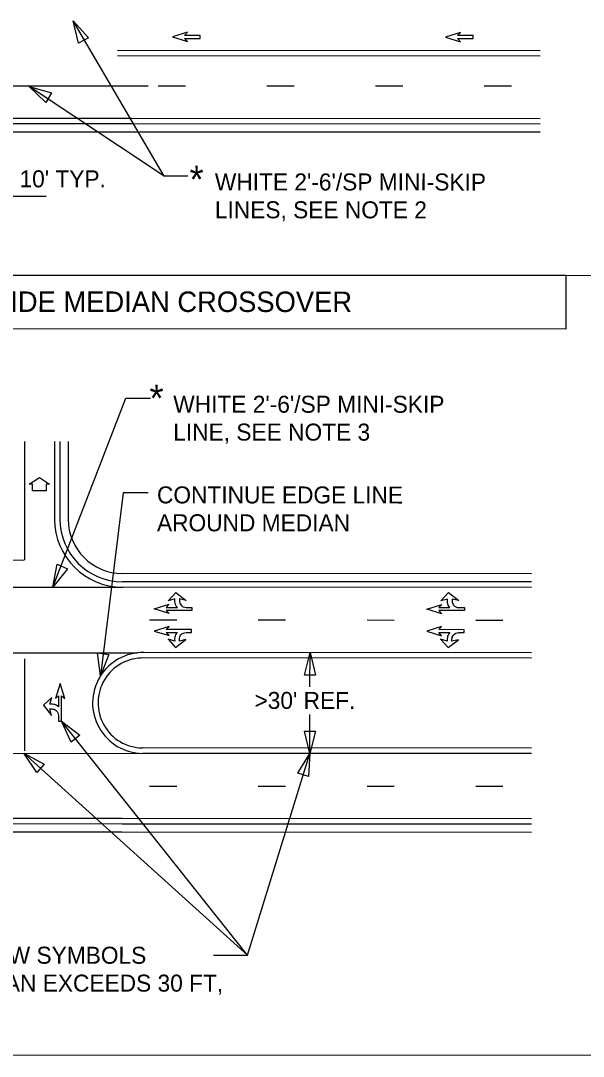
# Model space of a CAD drawing. Extents: x 50667 to 52386, y 46650 to 50479.
# Drawn here: x 51216.8 to 51454.8, y 46906.1 to 47344.1 of the extents above; entities that cross this region are included whole.
import ezdxf

# ---------------------------------------------------------------- set-up
doc = ezdxf.new("R2010")
doc.units = 0
for name, color, linetype in [('Default', 7, 'Continuous'), ('DEV TUBULAR MARKER SECTIONAL VIEW CELL', 7, 'Continuous'), ('Exist Hydro Spring Leader', 7, 'Continuous'), ('Exist Hydro Spring Text', 7, 'Continuous'), ('Gray Area Fill Shapes', 7, 'Continuous'), ('Matchline', 7, 'Continuous'), ('Prop EOT Dash', 7, 'Continuous'), ('Sheet North Arrow CELL', 7, 'Continuous')]:
    doc.layers.add(name, color=color, linetype=linetype)

msp = doc.modelspace()

# ---------------------------------------------------------------- linework, layer by layer
at = {"layer": 'Default'}
for p, q in [((51277.48, 47278.32), (51238.97, 47344.14)), ((51436.58, 47331.45), (51257.71, 47331.53)), ((51436.58, 47329.15), (51257.71, 47329.23)), ((51277.48, 47278.32), (51220.33, 47316.29)), ((51263.44, 47302.78), (51005.23, 47302.9)), ((51436.57, 47302.7), (51263.44, 47302.78)), ((51263.44, 47300.48), (51005.23, 47300.6)), ((51436.56, 47300.4), (51263.44, 47300.48)), ((51263.44, 47297.03), (51005.22, 47297.15)), ((51436.56, 47296.95), (51263.44, 47297.03)), ((51287.53, 47278.32), (51277.48, 47278.32)), ((51149.49, 47269.92), (51227.55, 47269.88)), ((52075.41, 47236.01), (50973.63, 47236.53)), ((51230.36, 47104.52), (51261.3, 47184.43)), ((51261.3, 47184.43), (51271.68, 47184.42)), ((51218.44, 47166.2), (51218.42, 47116.03)), ((51231.09, 47166.19), (51231.07, 47133.27)), ((51233.39, 47166.19), (51233.37, 47133.27)), ((51236.84, 47166.19), (51236.82, 47133.27)), ((51260.11, 47144.39), (51250.5, 47066.99)), ((51270.75, 47144.38), (51260.11, 47144.39)), ((51197.72, 47116.04), (51218.13, 47116.03)), ((51432.98, 47110.18), (51259.81, 47110.26)), ((51432.98, 47106.73), (51259.81, 47106.81)), ((51432.98, 47104.43), (51259.81, 47104.51)), ((51432.96, 47076.83), (51268.93, 47076.9)), ((51339.18, 47062.41), (51339.19, 47076.87)), ((51218.4, 47074.28), (51218.38, 47035.37)), ((51432.96, 47074.53), (51268.93, 47074.6)), ((51339.17, 47034.21), (51339.17, 47050.69)), ((51312.71, 46948.87), (51234.01, 47047.85)), ((51432.95, 47036.47), (51268.32, 47036.54)), ((51312.71, 46948.87), (51218.09, 47034.27)), ((51432.94, 47034.17), (51268.32, 47034.24)), ((51312.71, 46948.87), (51339.17, 47034.21)), ((51259.76, 47006.65), (51001.59, 47006.77)), ((51432.93, 47006.57), (51259.76, 47006.65)), ((51259.76, 47004.35), (51001.59, 47004.47)), ((51259.76, 47000.9), (51001.59, 47001.02)), ((51432.93, 47004.27), (51259.76, 47004.35)), ((51432.93, 47000.82), (51259.76, 47000.9)), ((51298.42, 46948.87), (51312.71, 46948.87))]:
    msp.add_line(p, q, dxfattribs=at)
for points in [[(51274.95, 47316.58), (51286.45, 47316.57)], [(51320.95, 47316.55), (51332.45, 47316.55)], [(51366.95, 47316.53), (51378.45, 47316.53)], [(51412.95, 47316.56), (51424.45, 47316.55)], [(51271.3, 47090.7), (51282.8, 47090.7)], [(51317.3, 47090.68), (51328.8, 47090.68)], [(51363.35, 47090.66), (51374.85, 47090.65)], [(51409.35, 47090.64), (51420.85, 47090.63)], [(51271.27, 47020.44), (51282.77, 47020.44)], [(51317.27, 47020.42), (51328.77, 47020.41)], [(51363.32, 47020.4), (51374.82, 47020.39)], [(51409.32, 47020.38), (51420.82, 47020.37)]]:
    msp.add_lwpolyline(points, dxfattribs=at)
for centre, radius, start, end in [((51259.84, 47133.3), 28.75, 179.9734, 269.9734), ((51259.84, 47133.3), 26.45, 179.9734, 269.9734), ((51259.84, 47133.3), 23, 179.9734, 269.9734), ((51268.52, 47055.57), 21.33, 88.898, 269.4602), ((51268.52, 47055.57), 19.03, 88.898, 269.4602)]:
    msp.add_arc(centre, radius, start, end, dxfattribs=at)
at = {"layer": 'DEV TUBULAR MARKER SECTIONAL VIEW CELL'}
for points in [[(50879.23, 46906.71), (50879.58, 47676.39), (52169.91, 47675.79), (52169.55, 46906.11)], [(50973.62, 47214), (51447.58, 47213.78), (51447.59, 47236.31), (50973.63, 47236.53)]]:
    msp.add_lwpolyline(points, close=True, dxfattribs=at)
at = {"layer": 'Exist Hydro Spring Leader'}
for p, q in [((51168.97, 47076.79), (51266.17, 47076.78)), ((51166.52, 47034.29), (51268.32, 47034.24))]:
    msp.add_line(p, q, dxfattribs=at)
at = {"layer": 'Exist Hydro Spring Text'}
for p, q in [((51171.06, 47316.61), (51270.68, 47316.57)), ((51174.73, 47104.59), (51259.83, 47104.55))]:
    msp.add_line(p, q, dxfattribs=at)
at = {"layer": 'Gray Area Fill Shapes'}
msp.add_lwpolyline([(51221.81, 47145.23), (51221.81, 47148.1), (51220.38, 47148.1), (51224.74, 47150.97), (51229, 47148.1), (51227.56, 47148.1), (51227.56, 47145.22)], close=True, dxfattribs=at)
at = {"layer": 'Matchline'}
for points in [[(51289.18, 47094.7), (51278.38, 47094.7), (51279.62, 47093.35), (51273.29, 47095.33), (51279.62, 47097.3), (51278.38, 47095.95), (51283.08, 47095.95), (51282.62, 47096.52), (51282.36, 47096.96), (51282.17, 47097.52), (51282.07, 47097.97), (51281.99, 47098.55), (51282.01, 47099.58), (51279.21, 47098.75), (51282.43, 47102.28), (51286.79, 47098.96), (51283.99, 47099.58), (51284, 47098.77), (51284.02, 47098.29), (51284.14, 47097.81), (51284.36, 47097.4), (51284.6, 47096.98), (51285.04, 47096.56), (51285.58, 47096.24), (51286.15, 47096.04), (51286.81, 47095.94), (51289.18, 47095.94)], [(51289.18, 47094.7), (51278.38, 47094.7), (51279.62, 47093.35), (51273.29, 47095.33), (51279.62, 47097.3), (51278.38, 47095.95), (51283.08, 47095.95), (51282.62, 47096.52), (51282.36, 47096.96), (51282.17, 47097.52), (51282.07, 47097.97), (51281.99, 47098.55), (51282.01, 47099.58), (51279.21, 47098.75), (51282.43, 47102.28), (51286.79, 47098.96), (51283.99, 47099.58), (51284, 47098.77), (51284.02, 47098.29), (51284.14, 47097.81), (51284.36, 47097.4), (51284.6, 47096.98), (51285.04, 47096.56), (51285.58, 47096.24), (51286.15, 47096.04), (51286.81, 47095.94), (51289.18, 47095.94)], [(51404.52, 47094.64), (51393.72, 47094.65), (51394.97, 47093.3), (51388.64, 47095.28), (51394.97, 47097.24), (51393.73, 47095.9), (51398.42, 47095.89), (51397.97, 47096.46), (51397.71, 47096.9), (51397.51, 47097.46), (51397.41, 47097.92), (51397.33, 47098.5), (51397.36, 47099.53), (51394.56, 47098.7), (51397.78, 47102.23), (51402.14, 47098.9), (51399.33, 47099.53), (51399.35, 47098.72), (51399.37, 47098.24), (51399.49, 47097.76), (51399.71, 47097.34), (51399.95, 47096.92), (51400.38, 47096.5), (51400.92, 47096.18), (51401.5, 47095.98), (51402.16, 47095.88), (51404.52, 47095.89)], [(51404.52, 47094.64), (51393.72, 47094.65), (51394.97, 47093.3), (51388.64, 47095.28), (51394.97, 47097.24), (51393.73, 47095.9), (51398.42, 47095.89), (51397.97, 47096.46), (51397.71, 47096.9), (51397.51, 47097.46), (51397.41, 47097.92), (51397.33, 47098.5), (51397.36, 47099.53), (51394.56, 47098.7), (51397.78, 47102.23), (51402.14, 47098.9), (51399.33, 47099.53), (51399.35, 47098.72), (51399.37, 47098.24), (51399.49, 47097.76), (51399.71, 47097.34), (51399.95, 47096.92), (51400.38, 47096.5), (51400.92, 47096.18), (51401.5, 47095.98), (51402.16, 47095.88), (51404.52, 47095.89)], [(51289.09, 47086.62), (51278.3, 47086.62), (51279.54, 47087.97), (51273.21, 47086), (51279.54, 47084.03), (51278.3, 47085.38), (51283, 47085.37), (51282.54, 47084.8), (51282.28, 47084.37), (51282.08, 47083.81), (51281.98, 47083.35), (51281.9, 47082.77), (51281.93, 47081.74), (51279.13, 47082.57), (51282.34, 47079.04), (51286.7, 47082.36), (51283.9, 47081.74), (51283.92, 47082.55), (51283.94, 47083.03), (51284.06, 47083.51), (51284.28, 47083.92), (51284.52, 47084.34), (51284.95, 47084.76), (51285.49, 47085.08), (51286.07, 47085.28), (51286.73, 47085.38), (51289.09, 47085.37)], [(51289.09, 47086.62), (51278.3, 47086.62), (51279.54, 47087.97), (51273.21, 47086), (51279.54, 47084.03), (51278.3, 47085.38), (51283, 47085.37), (51282.54, 47084.8), (51282.28, 47084.37), (51282.08, 47083.81), (51281.98, 47083.35), (51281.9, 47082.77), (51281.93, 47081.74), (51279.13, 47082.57), (51282.34, 47079.04), (51286.7, 47082.36), (51283.9, 47081.74), (51283.92, 47082.55), (51283.94, 47083.03), (51284.06, 47083.51), (51284.28, 47083.92), (51284.52, 47084.34), (51284.95, 47084.76), (51285.49, 47085.08), (51286.07, 47085.28), (51286.73, 47085.38), (51289.09, 47085.37)], [(51404.44, 47086.56), (51393.64, 47086.57), (51394.89, 47087.92), (51388.56, 47085.95), (51394.89, 47083.97), (51393.64, 47085.32), (51398.34, 47085.32), (51397.89, 47084.75), (51397.63, 47084.31), (51397.43, 47083.75), (51397.33, 47083.29), (51397.25, 47082.72), (51397.28, 47081.69), (51394.47, 47082.52), (51397.69, 47078.99), (51402.05, 47082.31), (51399.25, 47081.69), (51399.26, 47082.49), (51399.28, 47082.97), (51399.4, 47083.45), (51399.62, 47083.87), (51399.86, 47084.29), (51400.3, 47084.71), (51400.84, 47085.03), (51401.42, 47085.23), (51402.08, 47085.33), (51404.44, 47085.32)], [(51404.44, 47086.56), (51393.64, 47086.57), (51394.89, 47087.92), (51388.56, 47085.95), (51394.89, 47083.97), (51393.64, 47085.32), (51398.34, 47085.32), (51397.89, 47084.75), (51397.63, 47084.31), (51397.43, 47083.75), (51397.33, 47083.29), (51397.25, 47082.72), (51397.28, 47081.69), (51394.47, 47082.52), (51397.69, 47078.99), (51402.05, 47082.31), (51399.25, 47081.69), (51399.26, 47082.49), (51399.28, 47082.97), (51399.4, 47083.45), (51399.62, 47083.87), (51399.86, 47084.29), (51400.3, 47084.71), (51400.84, 47085.03), (51401.42, 47085.23), (51402.08, 47085.33), (51404.44, 47085.32)], [(51234.01, 47047.85), (51234.02, 47058.65), (51235.37, 47057.41), (51233.4, 47063.74), (51231.42, 47057.41), (51232.77, 47058.65), (51232.77, 47053.95), (51232.2, 47054.41), (51231.76, 47054.67), (51231.2, 47054.87), (51230.74, 47054.97), (51230.16, 47055.05), (51229.14, 47055.02), (51229.97, 47057.82), (51226.44, 47054.61), (51229.76, 47050.25), (51229.13, 47053.05), (51229.94, 47053.03), (51230.42, 47053.01), (51230.9, 47052.89), (51231.32, 47052.67), (51231.74, 47052.43), (51232.16, 47051.99), (51232.48, 47051.45), (51232.68, 47050.88), (51232.78, 47050.22), (51232.77, 47047.86)], [(51234.01, 47047.85), (51234.02, 47058.65), (51235.37, 47057.41), (51233.4, 47063.74), (51231.42, 47057.41), (51232.77, 47058.65), (51232.77, 47053.95), (51232.2, 47054.41), (51231.76, 47054.67), (51231.2, 47054.87), (51230.74, 47054.97), (51230.16, 47055.05), (51229.14, 47055.02), (51229.97, 47057.82), (51226.44, 47054.61), (51229.76, 47050.25), (51229.13, 47053.05), (51229.94, 47053.03), (51230.42, 47053.01), (51230.9, 47052.89), (51231.32, 47052.67), (51231.74, 47052.43), (51232.16, 47051.99), (51232.48, 47051.45), (51232.68, 47050.88), (51232.78, 47050.22), (51232.77, 47047.86)]]:
    msp.add_lwpolyline(points, close=True, dxfattribs=at)
at = {"layer": 'Prop EOT Dash'}
for points in [[(51241.28, 47334.64), (51238.98, 47344.14), (51245.49, 47336.84)], [(51241.28, 47334.64), (51238.98, 47344.14), (51245.49, 47336.84)], [(51227.38, 47309.52), (51220.33, 47316.29), (51229.74, 47313.63)], [(51227.38, 47309.52), (51220.33, 47316.29), (51229.74, 47313.63)], [(51236.52, 47112.24), (51230.36, 47104.52), (51232.16, 47114.23)], [(51236.52, 47112.24), (51230.36, 47104.52), (51232.16, 47114.23)], [(51254.02, 47076.12), (51250.5, 47066.99), (51249.31, 47076.7)], [(51254.02, 47076.12), (51250.5, 47066.99), (51249.31, 47076.7)], [(51336.81, 47067.38), (51339.19, 47076.87), (51341.55, 47067.38)], [(51336.81, 47067.38), (51339.19, 47076.87), (51341.55, 47067.38)], [(51238.06, 47038.95), (51234.01, 47047.85), (51241.77, 47041.9)], [(51238.06, 47038.95), (51234.01, 47047.85), (51241.77, 47041.9)], [(51341.54, 47043.7), (51339.17, 47034.21), (51336.8, 47043.7)], [(51341.54, 47043.7), (51339.17, 47034.21), (51336.8, 47043.7)], [(51223.54, 47026.15), (51218.09, 47034.27), (51226.72, 47029.67)], [(51223.54, 47026.15), (51218.09, 47034.27), (51226.72, 47029.67)], [(51334.09, 47025.85), (51339.17, 47034.21), (51338.62, 47024.44)], [(51334.09, 47025.85), (51339.17, 47034.21), (51338.62, 47024.44)]]:
    msp.add_lwpolyline(points, close=True, dxfattribs=at)
at = {"layer": 'Sheet North Arrow CELL'}
for points in [[(51287.28, 47335.29), (51286.03, 47336.64), (51292.68, 47336.63), (51292.68, 47337.88), (51286.03, 47337.88), (51287.28, 47339.23), (51280.95, 47337.26)], [(51287.28, 47335.29), (51286.03, 47336.64), (51292.68, 47336.63), (51292.68, 47337.88), (51286.03, 47337.88), (51287.28, 47339.23), (51280.95, 47337.26)], [(51402.86, 47335.23), (51401.61, 47336.58), (51408.26, 47336.58), (51408.26, 47337.82), (51401.61, 47337.83), (51402.86, 47339.18), (51396.52, 47337.21)], [(51402.86, 47335.23), (51401.61, 47336.58), (51408.26, 47336.58), (51408.26, 47337.82), (51401.61, 47337.83), (51402.86, 47339.18), (51396.52, 47337.21)]]:
    msp.add_lwpolyline(points, close=True, dxfattribs=at)

# ---------------------------------------------------------------- texts
at = {"layer": 'Default'}
for s, height, p in [("10' TYP.", 7.187, (51216.26, 47273.67)), ('*', 11.5, (51288.2, 47271.29)), ("WHITE 2'-6'/SP MINI-SKIP ", 7.1874, (51298.93, 47272.37)), ('LINES, SEE NOTE 2', 7.1874, (51298.93, 47260.58)), ('DIVIDED MULTI-LANE ROADWAY WITH WIDE MEDIAN CROSSOVER', 8.652, (50983.51, 47221.09)), ('*', 11.5, (51271.26, 47178.74)), ("WHITE 2'-6'/SP MINI-SKIP ", 7.1874, (51281.32, 47178.35)), ('LINE, SEE NOTE 3', 7.1874, (51281.31, 47166.56)), ('CONTINUE EDGE LINE', 7.1874, (51274.43, 47139.98)), ('AROUND MEDIAN ', 7.1874, (51274.43, 47128.19)), (">30' REF.", 7.187, (51315.68, 47053.05)), ('USE DOUBLE YELLOW CENTER LINE AND ARROW SYMBOLS', 7.1874, (50987.39, 46945.39)), ('IN MEDIAN CROSSOVER WHEN WIDTH OF MEDIAN EXCEEDS 30 FT,', 7.1874, (50987.38, 46933.6))]:
    msp.add_text(s, height=height, rotation=359.9734, dxfattribs=at).set_placement(p)

doc.saveas('drawing.dxf')
